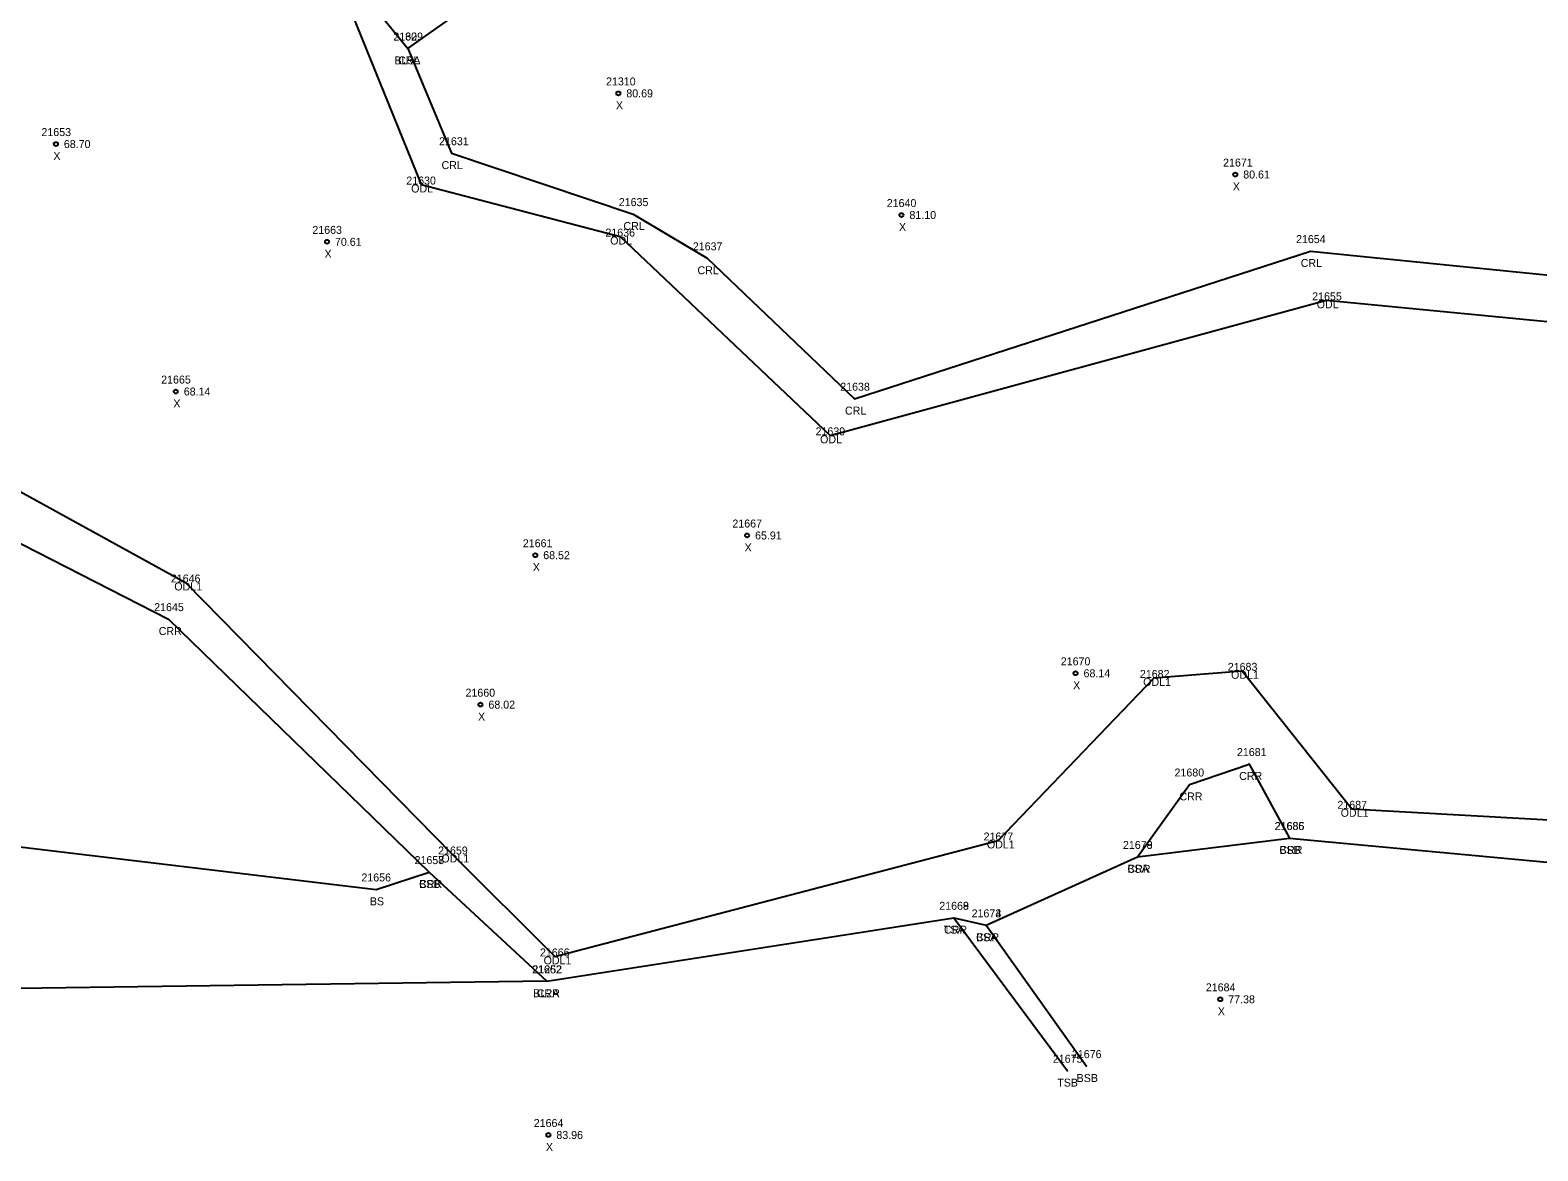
# Model space of a CAD drawing. Extents: x 2266664 to 2272385, y 716533 to 724777.
# Drawn here: x 2270024.3 to 2270213.7, y 721197.3 to 721338.1 of the extents above; entities that cross this region are included whole.
import ezdxf

# ---------------------------------------------------------------- set-up
doc = ezdxf.new("R2010")
doc.units = 0
for name, color, linetype in [('RD_DTM_BkLn1', 7, 'Continuous'), ('RD_DTM_BkLn2', 7, 'Continuous'), ('RD_EX_H2O', 7, 'Continuous'), ('RD_EX_H2O_txCode', 7, 'Continuous'), ('RD_Sketch8', 7, 'Continuous'), ('RD_SMD_Locator', 7, 'Continuous'), ('RD_SMD_Misc', 7, 'Continuous')]:
    doc.layers.add(name, color=color, linetype=linetype)

msp = doc.modelspace()

# ---------------------------------------------------------------- linework, layer by layer
at = {"layer": 'RD_DTM_BkLn1'}
for points in [[(2270071.72, 721335.84), (2270086.21, 721346.09), (2270121.72, 721393.06), (2270131.06, 721426.4), (2270135.6, 721460.59)], [(2270089.16, 721218.61), (2270010.6, 721217.53), (2269979.45, 721227.65), (2269977.14, 721240.81), (2269993.63, 721277.95), (2269987.72, 721285.71)]]:
    msp.add_lwpolyline(points, dxfattribs=at)
at = {"layer": 'RD_DTM_BkLn2'}
for p, q in [((2270163.36, 721234.25), (2270182.44, 721236.62)), ((2270140.31, 721226.6), (2270154.56, 721207.38)), ((2270144.35, 721225.65), (2270156.97, 721207.96))]:
    msp.add_line(p, q, dxfattribs=at)
msp.add_lwpolyline([(2270003.84, 721285.73), (2270014.08, 721278.19), (2269996.03, 721238.74), (2270067.72, 721230.16), (2270074.38, 721232.34)], dxfattribs=at)
at = {"layer": 'RD_EX_H2O'}
for points in [[(2270050.62, 721371.69), (2270058.64, 721361.22), (2270067.88, 721340.59), (2270071.72, 721335.84), (2270077.18, 721322.68), (2270100.02, 721315.03), (2270109.33, 721309.47), (2270127.84, 721291.83), (2270185.1, 721310.38), (2270243.87, 721304.44), (2270281.75, 721346.08), (2270379.45, 721379), (2270436.63, 721386.23), (2270462.17, 721399.02)], [(2270012.24, 721386.18), (2270049.51, 721368.82), (2270056.6, 721360.16), (2270073.38, 721318.74), (2270098.38, 721312.2), (2270124.75, 721287.22), (2270187.12, 721304.19), (2270246.02, 721298.52), (2270283.54, 721341.35), (2270380.7, 721373.75), (2270439.15, 721382.78), (2270465.18, 721395.03)], [(2269999.49, 721300.76), (2270016.26, 721283.84), (2270043.79, 721268.73), (2270077.34, 721234.55), (2270090.18, 721221.74), (2270145.86, 721236.31), (2270165.48, 721256.74), (2270176.53, 721257.63), (2270190.3, 721240.29), (2270233.77, 721237.87), (2270299.69, 721290.51), (2270389.09, 721327.36), (2270474.84, 721354.23)], [(2269996.97, 721296.88), (2270014.08, 721278.19), (2270041.67, 721264.13), (2270074.38, 721232.34), (2270089.16, 721218.61), (2270140.31, 721226.6), (2270144.35, 721225.65), (2270163.36, 721234.25), (2270169.88, 721243.35), (2270177.39, 721245.92), (2270182.44, 721236.62), (2270238.2, 721231.39), (2270303.78, 721285.16), (2270310.34, 721288.45), (2270391.6, 721320.78), (2270477.31, 721344.54)]]:
    msp.add_lwpolyline(points, dxfattribs=at)
at = {"layer": 'RD_SMD_Locator'}
for centre, radius in [((2270071.72, 721335.84), 0.001), ((2270071.72, 721335.84), 0.001), ((2270098.16, 721330.2), 0.25), ((2270027.51, 721323.83), 0.25), ((2270077.18, 721322.68), 0.001), ((2270175.65, 721320), 0.25), ((2270073.38, 721318.74), 0.001), ((2270100.02, 721315.03), 0.001), ((2270133.72, 721314.91), 0.25), ((2270061.56, 721311.54), 0.25), ((2270098.38, 721312.2), 0.001), ((2270109.33, 721309.47), 0.001), ((2270185.1, 721310.38), 0.001), ((2270187.12, 721304.19), 0.001), ((2270042.57, 721292.73), 0.25), ((2270127.84, 721291.83), 0.001), ((2270124.75, 721287.22), 0.001), ((2270114.33, 721274.64), 0.25), ((2270087.72, 721272.16), 0.25), ((2270043.79, 721268.73), 0.001), ((2270041.67, 721264.13), 0.001), ((2270155.59, 721257.32), 0.25), ((2270165.48, 721256.74), 0.001), ((2270176.53, 721257.63), 0.001), ((2270080.84, 721253.38), 0.25), ((2270177.39, 721245.92), 0.001), ((2270169.88, 721243.35), 0.001), ((2270190.3, 721240.29), 0.001), ((2270145.86, 721236.31), 0.001), ((2270182.44, 721236.62), 0.001), ((2270182.44, 721236.62), 0.001), ((2270077.34, 721234.55), 0.001), ((2270163.36, 721234.25), 0.001), ((2270163.36, 721234.25), 0.001), ((2270074.38, 721232.34), 0.001), ((2270074.38, 721232.34), 0.001), ((2270067.72, 721230.16), 0.001), ((2270140.31, 721226.6), 0.001), ((2270140.31, 721226.6), 0.001), ((2270144.35, 721225.65), 0.001), ((2270144.35, 721225.65), 0.001), ((2270090.18, 721221.74), 0.001), ((2270089.16, 721218.61), 0.001), ((2270089.16, 721218.61), 0.001), ((2270173.77, 721216.35), 0.25), ((2270154.56, 721207.38), 0.001), ((2270156.97, 721207.96), 0.001), ((2270089.37, 721199.3), 0.25)]:
    msp.add_circle(centre, radius, dxfattribs=at)

# ---------------------------------------------------------------- texts
at = {"layer": 'RD_EX_H2O_txCode'}
for s, p in [('21629', (2270069.9, 721336.84)), ('CRL', (2270070.49, 721333.84)), ('21631', (2270075.64, 721323.68)), ('CRL', (2270075.95, 721320.68)), ('21630', (2270071.52, 721318.74)), ('ODL', (2270072.13, 721317.74)), ('21635', (2270098.21, 721316.03)), ('21636', (2270096.53, 721312.2)), ('CRL', (2270098.8, 721313.03)), ('ODL', (2270097.13, 721311.2)), ('21637', (2270107.51, 721310.47)), ('21654', (2270183.28, 721311.38)), ('CRL', (2270183.87, 721308.38)), ('CRL', (2270108.1, 721307.47)), ('21655', (2270185.31, 721304.19)), ('ODL', (2270185.88, 721303.19)), ('21638', (2270126.03, 721292.83)), ('CRL', (2270126.62, 721289.83)), ('21639', (2270122.93, 721287.22)), ('ODL', (2270123.5, 721286.22)), ('21646', (2270041.95, 721268.73)), ('ODL1', (2270042.38, 721267.73)), ('21645', (2270039.85, 721265.13)), ('CRR', (2270040.42, 721262.13)), ('21682', (2270163.67, 721256.74)), ('21683', (2270174.71, 721257.63)), ('ODL1', (2270164.08, 721255.74)), ('ODL1', (2270175.12, 721256.63)), ('21681', (2270175.86, 721246.92)), ('21680', (2270168.02, 721244.35)), ('CRR', (2270176.14, 721243.92)), ('CRR', (2270168.63, 721241.35)), ('21687', (2270188.48, 721240.29)), ('ODL1', (2270188.89, 721239.29)), ('21677', (2270144.04, 721236.31)), ('21686', (2270180.59, 721237.62)), ('21659', (2270075.52, 721234.55)), ('ODL1', (2270144.45, 721235.31)), ('21678', (2270161.54, 721235.25)), ('CRR', (2270181.19, 721234.62)), ('21658', (2270072.56, 721233.34)), ('ODL1', (2270075.93, 721233.55)), ('CRR', (2270162.11, 721232.25)), ('CRR', (2270073.13, 721230.34)), ('21668', (2270138.47, 721227.6)), ('21673', (2270142.53, 721226.65)), ('CRR', (2270139.06, 721224.6)), ('CRR', (2270143.1, 721223.65)), ('21666', (2270088.31, 721221.74)), ('ODL1', (2270088.77, 721220.74)), ('21662', (2270087.32, 721219.61)), ('CRR', (2270087.91, 721216.61))]:
    msp.add_text(s, height=1, dxfattribs=at).set_placement(p)
at = {"layer": 'RD_Sketch8'}
for s, p in [('21310', (2270096.61, 721331.2)), ('80.69', (2270099.16, 721329.7)), ('X', (2270097.85, 721328.2)), ('21653', (2270025.69, 721324.83)), ('68.70', (2270028.51, 721323.33)), ('X', (2270027.19, 721321.83)), ('21671', (2270174.12, 721321)), ('80.61', (2270176.65, 721319.5)), ('X', (2270175.34, 721318)), ('21640', (2270131.87, 721315.91)), ('81.10', (2270134.72, 721314.41)), ('21663', (2270059.72, 721312.54)), ('X', (2270133.41, 721312.91)), ('70.61', (2270062.56, 721311.04)), ('X', (2270061.25, 721309.54)), ('21665', (2270040.73, 721293.73)), ('68.14', (2270043.57, 721292.23)), ('X', (2270042.26, 721290.73)), ('21667', (2270112.48, 721275.64)), ('65.91', (2270115.33, 721274.14)), ('21661', (2270086.16, 721273.16)), ('X', (2270114.01, 721272.64)), ('X', (2270087.41, 721270.16)), ('68.52', (2270088.72, 721271.66)), ('21670', (2270153.73, 721258.32)), ('68.14', (2270156.59, 721256.82)), ('X', (2270155.28, 721255.32)), ('21660', (2270078.96, 721254.38)), ('68.02', (2270081.84, 721252.88)), ('X', (2270080.53, 721251.38)), ('21684', (2270171.95, 721217.35)), ('77.38', (2270174.77, 721215.85)), ('X', (2270173.46, 721214.35)), ('21664', (2270087.53, 721200.3)), ('83.96', (2270090.37, 721198.8)), ('X', (2270089.06, 721197.3))]:
    msp.add_text(s, height=1, dxfattribs=at).set_placement(p)
at = {"layer": 'RD_SMD_Misc'}
for s, p in [('21309', (2270069.89, 721336.84)), ('BL5A', (2270070.03, 721333.84)), ('21685', (2270180.62, 721237.62)), ('21679', (2270161.54, 721235.25)), ('BSB', (2270181.19, 721234.62)), ('21657', (2270072.56, 721233.34)), ('BSA', (2270162.09, 721232.25)), ('21656', (2270065.88, 721231.16)), ('BSB', (2270073.13, 721230.34)), ('BS', (2270066.94, 721228.16)), ('21669', (2270138.47, 721227.6)), ('21674', (2270142.53, 721226.65)), ('TSA', (2270139.03, 721224.6)), ('BSA', (2270143.08, 721223.65)), ('21252', (2270087.37, 721219.61)), ('BL2A', (2270087.47, 721216.61)), ('21675', (2270152.74, 721208.38)), ('21676', (2270155.13, 721208.96)), ('BSB', (2270155.72, 721205.96)), ('TSB', (2270153.29, 721205.38))]:
    msp.add_text(s, height=1, dxfattribs=at).set_placement(p)

doc.saveas('drawing.dxf')
